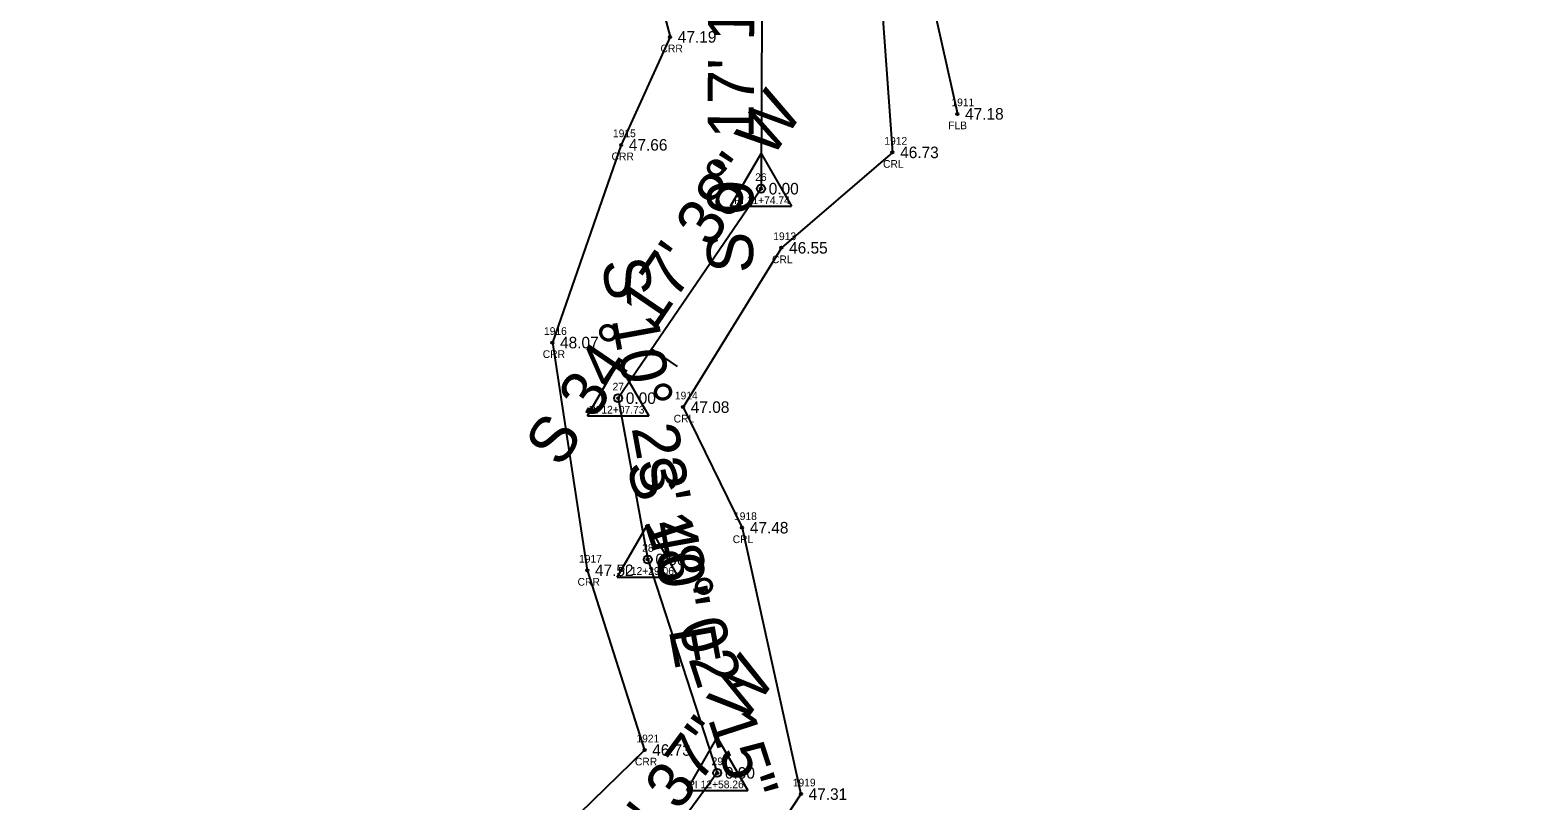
# Model space of a CAD drawing. Extents: x 2420113 to 2422887, y 845323 to 846653.
# Drawn here: x 2421748.2 to 2421944.3, y 845578.5 to 845678.8 of the extents above; entities that cross this region are included whole.
import ezdxf

# ---------------------------------------------------------------- set-up
doc = ezdxf.new("R2010")
doc.units = 0
for name, color, linetype in [('RD_EX_Fence_Other', 7, 'Continuous'), ('RD_EX_Fence_Other_txCode', 7, 'Continuous'), ('RD_EX_H2O', 7, 'Continuous'), ('RD_EX_H2O_txCode', 7, 'Continuous'), ('RD_EX_TX_Fence_Other_ELEV', 7, 'Continuous'), ('RD_EX_TX_H2O_ELEV', 7, 'Continuous'), ('RD_HC_Cl', 7, 'Continuous'), ('RD_HC_Data', 7, 'Continuous'), ('RD_HC_Data_Tic', 7, 'Continuous'), ('RD_HC_Survey_ELEV', 7, 'Continuous'), ('RD_HC_txCode', 7, 'Continuous'), ('RD_SMD_Locator', 7, 'Continuous')]:
    doc.layers.add(name, color=color, linetype=linetype)

msp = doc.modelspace()

# ---------------------------------------------------------------- linework, layer by layer
at = {"layer": 'RD_EX_Fence_Other'}
msp.add_lwpolyline([(2421828.48, 845790.12), (2421852.28, 845740.43), (2421864.73, 845686.16), (2421868.8, 845667.89)], dxfattribs=at)
at = {"layer": 'RD_EX_H2O'}
for points in [[(2421810.77, 845819.82), (2421810.76, 845810.56), (2421816.9, 845792.5), (2421822.4, 845786.03), (2421848.72, 845738.63), (2421858.75, 845685.13), (2421860.35, 845662.88), (2421845.9, 845650.47), (2421833.11, 845629.75), (2421840.79, 845614.06), (2421848.44, 845579.41), (2421832.04, 845554.52), (2421837.19, 845498.45), (2421811.62, 845484.13), (2421811.72, 845469.11), (2421841.99, 845438.03), (2421875.97, 845424.56), (2421900.41, 845383.13), (2421915.29, 845367.51)], [(2421768.08, 845778.29), (2421776.13, 845776.03), (2421785.06, 845769.58), (2421818.61, 845726.06), (2421831.42, 845677.9), (2421825.05, 845663.86), (2421816.1, 845638.14), (2421820.64, 845608.52), (2421828.09, 845585.14), (2421817.9, 845575.21), (2421808.75, 845549.61), (2421816.7, 845511.81), (2421785.75, 845489.97), (2421789.04, 845473.23), (2421801.09, 845449.66), (2421834.75, 845418.44), (2421870.95, 845402.12), (2421876.24, 845387.07), (2421866.97, 845385.32), (2421844.91, 845376.57), (2421842.84, 845344.63)]]:
    msp.add_lwpolyline(points, dxfattribs=at)
at = {"layer": 'RD_HC_Cl'}
for p, q in [((2421843.37, 845681.79), (2421843.25, 845658.16)), ((2421843.25, 845658.16), (2421824.66, 845630.91)), ((2421824.66, 845630.91), (2421828.51, 845609.93)), ((2421828.51, 845609.93), (2421837.55, 845582.17)), ((2421837.55, 845582.17), (2421823.57, 845563.22))]:
    msp.add_line(p, q, dxfattribs=at)
msp.add_arc((2421235.71, 846823.95), 1145.56, 264.46476, 308.21213, dxfattribs=at)
at = {"layer": 'RD_HC_Data'}
for p, q in [((2421839.28, 845655.87), (2421843.25, 845662.75)), ((2421843.25, 845662.75), (2421847.22, 845655.87)), ((2421839.28, 845655.87), (2421847.22, 845655.87)), ((2421820.69, 845628.61), (2421824.66, 845635.49)), ((2421824.66, 845635.49), (2421828.63, 845628.61)), ((2421820.69, 845628.61), (2421828.63, 845628.61)), ((2421824.54, 845607.64), (2421828.51, 845614.52)), ((2421828.51, 845614.52), (2421832.48, 845607.64)), ((2421824.54, 845607.64), (2421832.48, 845607.64)), ((2421833.58, 845579.87), (2421837.55, 845586.75)), ((2421837.55, 845586.75), (2421841.52, 845579.87)), ((2421833.58, 845579.87), (2421841.52, 845579.87))]:
    msp.add_line(p, q, dxfattribs=at)
for centre in [(2421843.25, 845658.16), (2421824.66, 845630.91), (2421828.51, 845609.93), (2421837.55, 845582.17)]:
    msp.add_circle(centre, 0.529, dxfattribs=at)
at = {"layer": 'RD_HC_Data_Tic'}
msp.add_line((2421829.02, 845637.29), (2421832.32, 845635.04), dxfattribs=at)
at = {"layer": 'RD_SMD_Locator'}
for centre in [(2421831.42, 845677.9), (2421868.8, 845667.89), (2421825.05, 845663.86), (2421860.35, 845662.88), (2421843.25, 845658.16), (2421845.9, 845650.47), (2421816.1, 845638.14), (2421824.66, 845630.91), (2421833.11, 845629.75), (2421840.79, 845614.06), (2421820.64, 845608.52), (2421828.51, 845609.93), (2421828.09, 845585.14), (2421837.55, 845582.17), (2421848.44, 845579.41)]:
    msp.add_circle(centre, 0.15, dxfattribs=at)

# ---------------------------------------------------------------- texts
at = {"layer": 'RD_EX_Fence_Other_txCode'}
for s, p in [('1911', (2421868.02, 845668.89)), ('FLB', (2421867.6, 845665.89))]:
    msp.add_text(s, height=1, dxfattribs=at).set_placement(p)
at = {"layer": 'RD_EX_H2O_txCode'}
for s, p in [('CRR', (2421830.17, 845675.9)), ('1915', (2421823.98, 845664.86)), ('1912', (2421859.29, 845663.88)), ('CRR', (2421823.8, 845661.86)), ('CRL', (2421859.12, 845660.88)), ('1913', (2421844.84, 845651.47)), ('CRL', (2421844.67, 845648.47)), ('1916', (2421815.01, 845639.14)), ('CRR', (2421814.85, 845636.14)), ('1914', (2421832.04, 845630.75)), ('CRL', (2421831.88, 845627.75)), ('1918', (2421839.73, 845615.06)), ('CRL', (2421839.56, 845612.06)), ('1917', (2421819.57, 845609.52)), ('CRR', (2421819.38, 845606.52)), ('1921', (2421827.03, 845586.14)), ('CRR', (2421826.84, 845583.14)), ('1919', (2421847.38, 845580.41))]:
    msp.add_text(s, height=1, dxfattribs=at).set_placement(p)
at = {"layer": 'RD_EX_TX_Fence_Other_ELEV'}
msp.add_text('47.18', height=1.5, dxfattribs=at).set_placement((2421869.8, 845667.14))
at = {"layer": 'RD_EX_TX_H2O_ELEV'}
for s, p in [('47.19', (2421832.42, 845677.15)), ('47.66', (2421826.05, 845663.11)), ('46.73', (2421861.35, 845662.13)), ('46.55', (2421846.9, 845649.72)), ('48.07', (2421817.1, 845637.39)), ('47.08', (2421834.11, 845629)), ('47.48', (2421841.79, 845613.31)), ('47.52', (2421821.64, 845607.77)), ('46.73', (2421829.09, 845584.39)), ('47.31', (2421849.44, 845578.66))]:
    msp.add_text(s, height=1.5, dxfattribs=at).set_placement(p)
at = {"layer": 'RD_HC_Data'}
for s, rotation, p in [('S 0%%d 17\' 11" W', 89.7137, (2421842.2, 845647.19)), ('S 34%%d 17\' 38" W', 55.7061, (2421817.17, 845621.7)), ('S 10%%d 23\' 40" E', 280.3944, (2421822.43, 845648.64)), ('S 18%%d 02\' 15" E', 288.0376, (2421825.58, 845622.16)), ('S 36%%d 25\' 37" W', 53.5731, (2421811.98, 845549.2))]:
    msp.add_text(s, height=6, rotation=rotation, dxfattribs=at).set_placement(p)
at = {"layer": 'RD_HC_Survey_ELEV'}
for p in [(2421844.25, 845657.41), (2421825.66, 845630.16), (2421829.51, 845609.18), (2421838.55, 845581.42)]:
    msp.add_text('0.00', height=1.5, dxfattribs=at).set_placement(p)
at = {"layer": 'RD_HC_txCode'}
for s, p in [('26', (2421842.49, 845659.16)), ('PI 11+74.74', (2421839.75, 845656.16)), ('27', (2421823.93, 845631.91)), ('PI 12+07.73', (2421820.84, 845628.91)), ('28', (2421827.78, 845610.93)), ('PI 12+29.06', (2421824.67, 845607.93)), ('29', (2421836.82, 845583.17)), ('PI 12+58.26', (2421833.75, 845580.17))]:
    msp.add_text(s, height=1, dxfattribs=at).set_placement(p)

doc.saveas('drawing.dxf')
